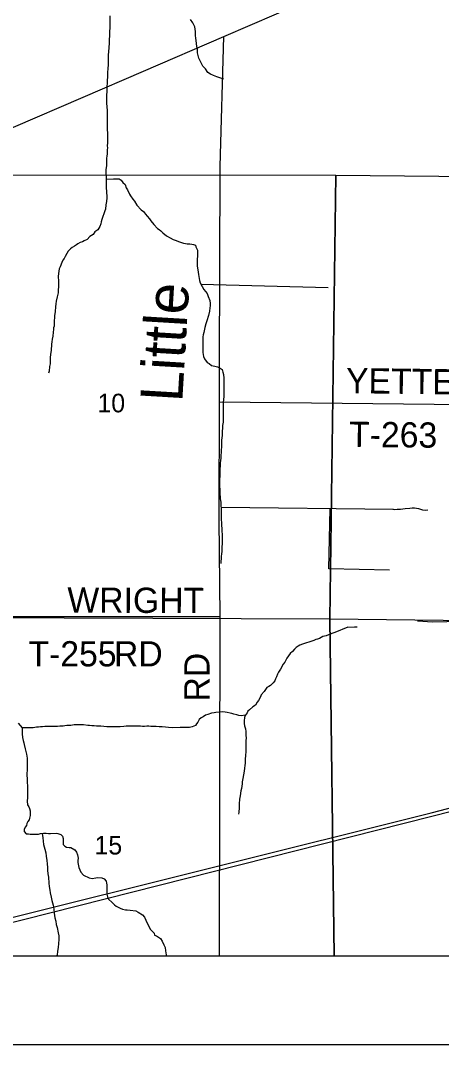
# Model space of a CAD drawing. Extents: x 0 to 34, y 0 to 22.
# Drawn here: x 4.883 to 5.357, y 14 to 15.153 of the extents above; entities that cross this region are included whole.
import ezdxf

# ---------------------------------------------------------------- set-up
doc = ezdxf.new("R2010")
doc.units = 0
for name, color, linetype in [('GM_X_Corporation', 7, 'Continuous'), ('GM_X_Minor_River', 7, 'Continuous'), ('GM_X_Minor_River_Text', 7, 'Continuous'), ('GM_X_Rail_Line', 7, 'Continuous'), ('GM_X_Section_Text', 7, 'Continuous'), ('GM_X_Township_Road', 7, 'Continuous'), ('GM_X_Township_Road_Text', 7, 'Continuous'), ('GM_X_US_Route', 7, 'Continuous'), ('SH_Data', 7, 'Continuous')]:
    doc.layers.add(name, color=color, linetype=linetype)

msp = doc.modelspace()

# ---------------------------------------------------------------- linework, layer by layer
at = {"layer": 'GM_X_Corporation'}
for points in [[(4.7426, 14.9789), (5.238, 14.9786), (5.2314, 14.4786), (4.7326, 14.4807)], [(5.238, 14.9786), (5.741, 14.9736), (5.7415, 14.4729), (5.2314, 14.4786)], [(4.7299, 14.1), (5.2363, 14.1), (5.2314, 14.4786), (4.7326, 14.4807)], [(5.2363, 14.1), (5.7461, 14.1), (5.7415, 14.4729), (5.2314, 14.4786)]]:
    msp.add_lwpolyline(points, close=True, dxfattribs=at)
for points in [[(2.1, 14.1), (6.0569, 14.1)], [(3.2397, 14.1), (6.0569, 14.1)]]:
    msp.add_lwpolyline(points, dxfattribs=at)
at = {"layer": 'GM_X_Minor_River'}
for p, q in [((5.0862, 14.8559), (5.2293, 14.852)), ((5.3031, 14.6023), (5.1088, 14.6043)), ((5.2301, 14.5355), (5.2317, 14.603)), ((5.2984, 14.5339), (5.2301, 14.5355)), ((5.2301, 14.5355), (5.2301, 14.5355)), ((5.3299, 14.4768), (5.3307, 14.477)), ((5.3307, 14.477), (5.3466, 14.4757)), ((5.3466, 14.4757), (5.3793, 14.4765))]:
    msp.add_line(p, q, dxfattribs=at)
for points in [[(4.9838, 15.1578), (4.9838, 15.1511), (4.9838, 15.1485), (4.9836, 15.1437), (4.9833, 15.1409), (4.9831, 15.1376), (4.9831, 15.1354), (4.9829, 15.1314), (4.9828, 15.1291), (4.9828, 15.1264), (4.9824, 15.1232), (4.9823, 15.1167), (4.9819, 15.1146), (4.9817, 15.1124), (4.9817, 15.1059), (4.9816, 15.1025), (4.9814, 15.0989), (4.9812, 15.0939), (4.9811, 15.0915), (4.9809, 15.0882), (4.9807, 15.0863), (4.9807, 15.0843), (4.9805, 15.0824), (4.9804, 15.078)], [(5.1118, 15.0865), (5.1086, 15.0877), (5.1042, 15.0892), (5.1005, 15.0908), (5.0969, 15.0924), (5.0941, 15.0942), (5.0912, 15.0983), (5.0884, 15.1012), (5.087, 15.1041), (5.0852, 15.1072), (5.0838, 15.1101), (5.0829, 15.1131), (5.0824, 15.1164), (5.0822, 15.1204), (5.0817, 15.1232), (5.0812, 15.1271), (5.0806, 15.1328), (5.0801, 15.1358), (5.0801, 15.1402), (5.0795, 15.1455), (5.0771, 15.1502), (5.0746, 15.1539)], [(4.9804, 15.078), (4.9804, 15.0748), (4.9802, 15.0725), (4.98, 15.0689), (4.9799, 15.0655), (4.9799, 15.0609), (4.9803, 15.0544), (4.9805, 15.0525), (4.9805, 15.0503), (4.9805, 15.0468), (4.9807, 15.0408), (4.9809, 15.0149), (4.9807, 15.0117), (4.9809, 15.0092), (4.9807, 15.0072), (4.9806, 15.0022), (4.9804, 15.0003), (4.98, 14.9973), (4.98, 14.9954), (4.9798, 14.9935), (4.9797, 14.9895), (4.9793, 14.9845), (4.9794, 14.9726), (4.9796, 14.9665), (4.9796, 14.9639), (4.9798, 14.9606), (4.98, 14.9582), (4.9802, 14.9557), (4.9802, 14.9532), (4.9799, 14.949), (4.9793, 14.9452), (4.9788, 14.9403), (4.978, 14.9384), (4.9769, 14.935), (4.9758, 14.9319), (4.9748, 14.9287), (4.9737, 14.926), (4.9734, 14.9238), (4.9722, 14.9209), (4.97, 14.9171), (4.9669, 14.9148), (4.9647, 14.9119), (4.9611, 14.9095), (4.9581, 14.9062), (4.9549, 14.9045), (4.953, 14.9037), (4.9503, 14.9026), (4.9478, 14.9012), (4.946, 14.9003), (4.9437, 14.8988), (4.9412, 14.897), (4.9393, 14.8957), (4.9367, 14.893), (4.9352, 14.8902), (4.9333, 14.8871), (4.9322, 14.8847), (4.9309, 14.8828), (4.9297, 14.8801), (4.9279, 14.8753), (4.9267, 14.8732), (4.9262, 14.8706), (4.9256, 14.8649), (4.9256, 14.863), (4.9258, 14.8607), (4.9259, 14.8535), (4.9255, 14.8486), (4.9255, 14.8461), (4.9242, 14.8417), (4.9233, 14.8368), (4.9228, 14.8337), (4.9224, 14.8305), (4.922, 14.825), (4.9215, 14.8201), (4.9213, 14.8182), (4.9211, 14.8147), (4.9208, 14.8087), (4.9204, 14.8068), (4.9202, 14.8049), (4.9199, 14.802), (4.9193, 14.7973), (4.9186, 14.794), (4.9184, 14.791), (4.918, 14.7883), (4.9175, 14.7813), (4.9171, 14.7792), (4.917, 14.7767), (4.9166, 14.7733), (4.9164, 14.768), (4.9163, 14.7661), (4.9159, 14.7633), (4.9152, 14.7579), (4.9146, 14.7558)], [(4.9794, 14.9741), (4.9877, 14.9743), (4.9915, 14.9745), (4.9942, 14.9744), (4.9963, 14.9728), (4.9984, 14.9702), (5.0008, 14.9679), (5.0022, 14.9643), (5.0037, 14.9622), (5.0056, 14.9573), (5.007, 14.9552), (5.0097, 14.9516), (5.0114, 14.9494), (5.0142, 14.9448), (5.0188, 14.9397), (5.0215, 14.9376), (5.0236, 14.9348), (5.0257, 14.9323), (5.0284, 14.9295), (5.0299, 14.927), (5.0331, 14.9232), (5.0372, 14.9185), (5.0391, 14.9174), (5.0412, 14.9159), (5.0433, 14.9136), (5.0473, 14.9104), (5.0516, 14.9079), (5.0551, 14.9062), (5.0583, 14.9049), (5.0608, 14.9038), (5.063, 14.9032), (5.0665, 14.9021), (5.0687, 14.9015), (5.0706, 14.9013), (5.0737, 14.9014), (5.0761, 14.9008), (5.078, 14.9004), (5.0799, 14.8999), (5.0803, 14.898), (5.0823, 14.894), (5.0823, 14.8868), (5.0821, 14.8847), (5.0818, 14.8809), (5.0818, 14.8761), (5.0826, 14.872), (5.0833, 14.8668), (5.0841, 14.8621), (5.0847, 14.86), (5.0855, 14.8573), (5.0876, 14.8534), (5.0895, 14.8498), (5.0912, 14.8477), (5.0931, 14.8454), (5.0945, 14.8418), (5.0962, 14.8373), (5.0966, 14.834), (5.0964, 14.8314), (5.0962, 14.8291), (5.0957, 14.8255), (5.0946, 14.8205), (5.0929, 14.8146), (5.0916, 14.8112), (5.0907, 14.8072), (5.0896, 14.8013), (5.0886, 14.7987), (5.0884, 14.7966), (5.0883, 14.7939), (5.0883, 14.7829), (5.0885, 14.7791), (5.0889, 14.7746), (5.0903, 14.7719), (5.0931, 14.7676), (5.0956, 14.7664), (5.0979, 14.7645), (5.0998, 14.7638), (5.1017, 14.7634), (5.1049, 14.7629), (5.108, 14.7615), (5.1099, 14.7598), (5.1108, 14.757), (5.1114, 14.754), (5.112, 14.75), (5.1121, 14.7353), (5.1119, 14.7293), (5.1112, 14.7226), (5.1113, 14.7051), (5.1111, 14.7004), (5.1106, 14.6968), (5.1106, 14.6949), (5.11, 14.6894), (5.1101, 14.6856), (5.1095, 14.6803), (5.1094, 14.6738), (5.1087, 14.662), (5.1085, 14.6599), (5.1083, 14.6575), (5.1079, 14.6542), (5.1078, 14.6508), (5.1076, 14.6482), (5.1074, 14.6444), (5.1073, 14.6398)], [(5.1073, 14.6398), (5.1071, 14.6364), (5.1071, 14.6286), (5.1073, 14.6248), (5.1074, 14.6214), (5.1076, 14.6191), (5.1079, 14.617), (5.108, 14.6144), (5.1085, 14.6104), (5.1087, 14.6083), (5.1088, 14.6014), (5.109, 14.5996), (5.109, 14.591), (5.1092, 14.5874), (5.1097, 14.5779), (5.1099, 14.5741), (5.1099, 14.5709), (5.1101, 14.5667), (5.1099, 14.5635), (5.1097, 14.5601), (5.1098, 14.558), (5.1096, 14.5549), (5.1094, 14.5525), (5.109, 14.5492), (5.1091, 14.5469), (5.1087, 14.5437), (5.1087, 14.5416)], [(5.3414, 14.6014), (5.3387, 14.6012), (5.3361, 14.6016), (5.3338, 14.6022), (5.3315, 14.603), (5.3289, 14.6035), (5.3266, 14.6039), (5.3238, 14.6036), (5.3215, 14.6032), (5.3162, 14.6028), (5.3133, 14.6026), (5.3107, 14.6023), (5.3072, 14.6021), (5.3046, 14.6017), (5.3023, 14.6021)], [(5.2516, 14.4698), (5.2368, 14.4639), (5.2334, 14.4625), (5.227, 14.4602), (5.2234, 14.4591), (5.2196, 14.4572), (5.2175, 14.4564), (5.2156, 14.4558), (5.2133, 14.4549), (5.2086, 14.4533), (5.2037, 14.4516), (5.2006, 14.4505), (5.1976, 14.4495), (5.1957, 14.4485), (5.1933, 14.4468), (5.1914, 14.4449), (5.1891, 14.4424), (5.1868, 14.4401), (5.1846, 14.4375), (5.1829, 14.4348), (5.1806, 14.4304), (5.1787, 14.4283), (5.1759, 14.4226), (5.1735, 14.419), (5.1722, 14.4167), (5.1712, 14.4139), (5.1703, 14.4116), (5.1695, 14.4093), (5.1675, 14.407), (5.1646, 14.404), (5.1625, 14.403), (5.1603, 14.4017), (5.1573, 14.3973), (5.1539, 14.3937), (5.1533, 14.3912), (5.151, 14.3872), (5.1493, 14.3853), (5.1475, 14.3819), (5.1446, 14.3802), (5.1408, 14.3769), (5.139, 14.3754), (5.1382, 14.3735), (5.1361, 14.3704), (5.1352, 14.368), (5.1348, 14.3644), (5.1349, 14.3615), (5.1354, 14.3589), (5.1362, 14.3554), (5.1366, 14.3522), (5.1366, 14.3486), (5.137, 14.3446), (5.1368, 14.3425), (5.1369, 14.3389), (5.1367, 14.3336), (5.1367, 14.3302), (5.1364, 14.3251), (5.136, 14.3216), (5.1358, 14.3165), (5.1357, 14.3144), (5.1351, 14.3108), (5.1347, 14.308), (5.1344, 14.3055), (5.134, 14.3034), (5.1333, 14.2994), (5.1325, 14.2956), (5.1325, 14.2933), (5.1318, 14.2882), (5.1311, 14.2857), (5.1303, 14.2798), (5.1296, 14.276), (5.1292, 14.2711), (5.1291, 14.2683), (5.1291, 14.2664), (5.1287, 14.2616), (5.1283, 14.2593)], [(5.2513, 14.4697), (5.259, 14.47), (5.2622, 14.4703)], [(5.1363, 14.3707), (5.1314, 14.3701), (5.1287, 14.3704), (5.1265, 14.3712), (5.1234, 14.3717), (5.1211, 14.3725), (5.119, 14.373), (5.1158, 14.3738), (5.1133, 14.3742), (5.1107, 14.3743), (5.1076, 14.3741), (5.1031, 14.3737), (5.1012, 14.3735), (5.098, 14.3728), (5.094, 14.3714), (5.0912, 14.3707), (5.0887, 14.3687), (5.0866, 14.3678), (5.0843, 14.3657), (5.0827, 14.363), (5.0813, 14.3611), (5.08, 14.359), (5.0764, 14.3575), (5.0734, 14.3569), (5.0715, 14.3567), (5.0673, 14.3569), (5.0628, 14.3567), (5.054, 14.3566), (5.0497, 14.3568), (5.0462, 14.3572), (5.0424, 14.3575), (5.0392, 14.3577), (5.0358, 14.3579), (5.0337, 14.3579), (5.0299, 14.3581), (5.0274, 14.3582), (5.0254, 14.3582), (5.0225, 14.358), (5.0204, 14.358), (5.0183, 14.3582), (5.0163, 14.3582), (5.0123, 14.3584), (5.0098, 14.3584), (5.0045, 14.3582), (5.002, 14.3582), (4.9995, 14.358), (4.9952, 14.3577), (4.9925, 14.3575), (4.984, 14.3575), (4.9802, 14.3577), (4.9768, 14.3579), (4.9734, 14.3582), (4.9711, 14.3584), (4.9688, 14.3584), (4.9661, 14.3586), (4.9635, 14.3589), (4.9608, 14.3591), (4.9589, 14.3591), (4.954, 14.3597), (4.9517, 14.3599), (4.9489, 14.3598), (4.947, 14.36), (4.9434, 14.3598), (4.9415, 14.3596), (4.9396, 14.3592), (4.9373, 14.3592), (4.9352, 14.359), (4.9331, 14.3586), (4.9312, 14.3583), (4.9272, 14.3582), (4.9246, 14.358), (4.9223, 14.358), (4.9177, 14.358), (4.9136, 14.3578), (4.9103, 14.3578), (4.9077, 14.3576), (4.9056, 14.3576), (4.9035, 14.3574), (4.9011, 14.3572), (4.8992, 14.357), (4.8973, 14.3566), (4.8849, 14.3564)], [(4.8805, 14.3617), (4.885, 14.3564)], [(4.885, 14.3564), (4.8851, 14.3499), (4.8855, 14.3457), (4.8861, 14.3423), (4.8867, 14.3395), (4.8873, 14.3376), (4.8885, 14.3328), (4.8898, 14.3268), (4.8904, 14.3247), (4.8906, 14.3222), (4.8906, 14.3154), (4.8905, 14.3091), (4.8903, 14.3047), (4.8907, 14.2975), (4.8905, 14.295), (4.8908, 14.2911), (4.891, 14.288), (4.891, 14.2781), (4.8905, 14.2738), (4.8911, 14.2698), (4.8924, 14.2677), (4.8934, 14.2658), (4.8939, 14.2632), (4.894, 14.2577), (4.8934, 14.2548), (4.8927, 14.2529), (4.8913, 14.251), (4.8902, 14.2487), (4.8897, 14.2466), (4.8885, 14.2447), (4.8872, 14.2421), (4.8872, 14.2396), (4.8893, 14.2373), (4.892, 14.2371), (4.8941, 14.2368), (4.896, 14.2366), (4.9003, 14.2366), (4.9032, 14.2368), (4.9056, 14.2374), (4.9091, 14.2378), (4.9119, 14.2378), (4.9146, 14.2376), (4.917, 14.2376), (4.9233, 14.2378), (4.9252, 14.2376), (4.9286, 14.2365), (4.9305, 14.2346), (4.9311, 14.232), (4.9311, 14.2253), (4.9329, 14.2231), (4.9348, 14.2223), (4.938, 14.2219), (4.9399, 14.2216), (4.9443, 14.2193), (4.946, 14.2166), (4.9473, 14.2134), (4.9479, 14.2098), (4.9477, 14.2073), (4.9476, 14.2047), (4.9489, 14.1992), (4.951, 14.1941), (4.9539, 14.1907), (4.9604, 14.1876), (4.9636, 14.1869), (4.9678, 14.1877), (4.97, 14.1881), (4.9748, 14.1875), (4.9773, 14.1864), (4.9795, 14.1839), (4.9797, 14.1818), (4.9803, 14.1796), (4.9803, 14.1773), (4.9802, 14.1748), (4.9802, 14.1693), (4.9812, 14.1663), (4.9823, 14.1636), (4.9863, 14.1598), (4.9888, 14.1574), (4.9907, 14.1557), (4.9951, 14.1536), (4.9979, 14.1525), (5.0013, 14.1517), (5.0032, 14.1515), (5.0065, 14.1514), (5.0129, 14.1504), (5.0154, 14.1491), (5.0204, 14.1459), (5.0228, 14.1433), (5.0257, 14.1366), (5.028, 14.1323), (5.0292, 14.13), (5.0334, 14.1253), (5.0339, 14.1232), (5.036, 14.1222), (5.0408, 14.1192), (5.0425, 14.1164), (5.0446, 14.1122), (5.0458, 14.1092), (5.0464, 14.1054), (5.047, 14.1008), (5.047, 14.1)], [(4.9076, 14.2376), (4.9081, 14.2326), (4.9085, 14.229), (4.9089, 14.225), (4.9105, 14.2199), (4.9116, 14.2156), (4.912, 14.212), (4.9126, 14.207), (4.913, 14.2032), (4.9136, 14.1992), (4.9136, 14.1962), (4.914, 14.192), (4.9146, 14.1882), (4.915, 14.1818), (4.9154, 14.178), (4.916, 14.1736), (4.9164, 14.1706), (4.9176, 14.166), (4.9184, 14.162), (4.9197, 14.1567), (4.9205, 14.1524), (4.9211, 14.1478), (4.9219, 14.1427), (4.9228, 14.1389), (4.9234, 14.1351), (4.9242, 14.1317), (4.9254, 14.1256), (4.9261, 14.1222), (4.9262, 14.1186), (4.9258, 14.1135), (4.9255, 14.1095), (4.9249, 14.1047), (4.9242, 14.1009), (4.9239, 14.1)]]:
    msp.add_lwpolyline(points, dxfattribs=at)
at = {"layer": 'GM_X_Rail_Line'}
for points in [[(4.71, 14.1), (4.8549, 14.1384), (5.3454, 14.2609), (5.6152, 14.3308), (5.7933, 14.3766), (5.9459, 14.4132), (6.0467, 14.4393), (6.0487, 14.4397)], [(4.7293, 14.1), (4.8549, 14.133), (5.3459, 14.257), (5.6188, 14.3266), (5.8029, 14.3731), (5.9465, 14.4099), (6.0459, 14.4344), (6.0488, 14.4351)]]:
    msp.add_lwpolyline(points, dxfattribs=at)
at = {"layer": 'GM_X_Township_Road'}
msp.add_line((5.1071, 14.7234), (5.6148, 14.7179), dxfattribs=at)
for points in [[(5.1072, 14.764), (5.1078, 14.9882), (5.1121, 15.1348)], [(5.1068, 14.595), (5.1071, 14.7234), (5.1072, 14.7635), (5.1072, 14.764)], [(5.1072, 14.1), (5.108, 14.4818), (5.1068, 14.5911), (5.1068, 14.595)], [(4.8598, 14.4817), (4.893, 14.4818), (4.9751, 14.4817), (5.069, 14.4819), (5.108, 14.4818)]]:
    msp.add_lwpolyline(points, dxfattribs=at)
at = {"layer": 'GM_X_US_Route'}
msp.add_lwpolyline([(4.4839, 14.8618), (4.5365, 14.885), (4.6169, 14.9206), (4.7426, 14.9753), (4.8019, 15.0011), (4.8751, 15.0327), (4.9535, 15.0664), (5.0215, 15.0957), (5.1121, 15.1348), (5.2304, 15.1861), (5.319, 15.2247), (5.466, 15.2883), (5.5728, 15.3298), (5.6214, 15.3487), (5.7487, 15.3997), (5.8221, 15.4287), (5.9013, 15.458), (5.9891, 15.4931)], dxfattribs=at)
at = {"layer": 'SH_Data'}
for p, q in [((2.1, 14.1), (8.9, 14.1)), ((2.1, 14.1), (8.9, 14.1)), ((2, 14), (9, 14)), ((2, 14), (9, 14))]:
    msp.add_line(p, q, dxfattribs=at)

# ---------------------------------------------------------------- texts
at = {"layer": 'GM_X_Minor_River_Text'}
msp.add_text('Little', height=0.04738, rotation=86.5973, dxfattribs=at).set_placement((5.0651, 14.7225))
at = {"layer": 'GM_X_Section_Text'}
for s, p in [('10', (4.9697, 14.7116)), ('15', (4.9664, 14.2139))]:
    msp.add_text(s, height=0.02093, rotation=0, dxfattribs=at).set_placement(p)
at = {"layer": 'GM_X_Township_Road_Text'}
for s, rotation, p in [('YETTER', 359.2813, (5.2493, 14.7332)), ('T-263', 359.4386, (5.2528, 14.6727)), ('WRIGHT', 359.828, (4.9358, 14.4861)), ('T-255', 0, (4.892, 14.4256)), ('RD', 0, (4.9883, 14.4256)), ('RD', 90, (5.0959, 14.3861))]:
    msp.add_text(s, height=0.02841, rotation=rotation, dxfattribs=at).set_placement(p)

doc.saveas('drawing.dxf')
